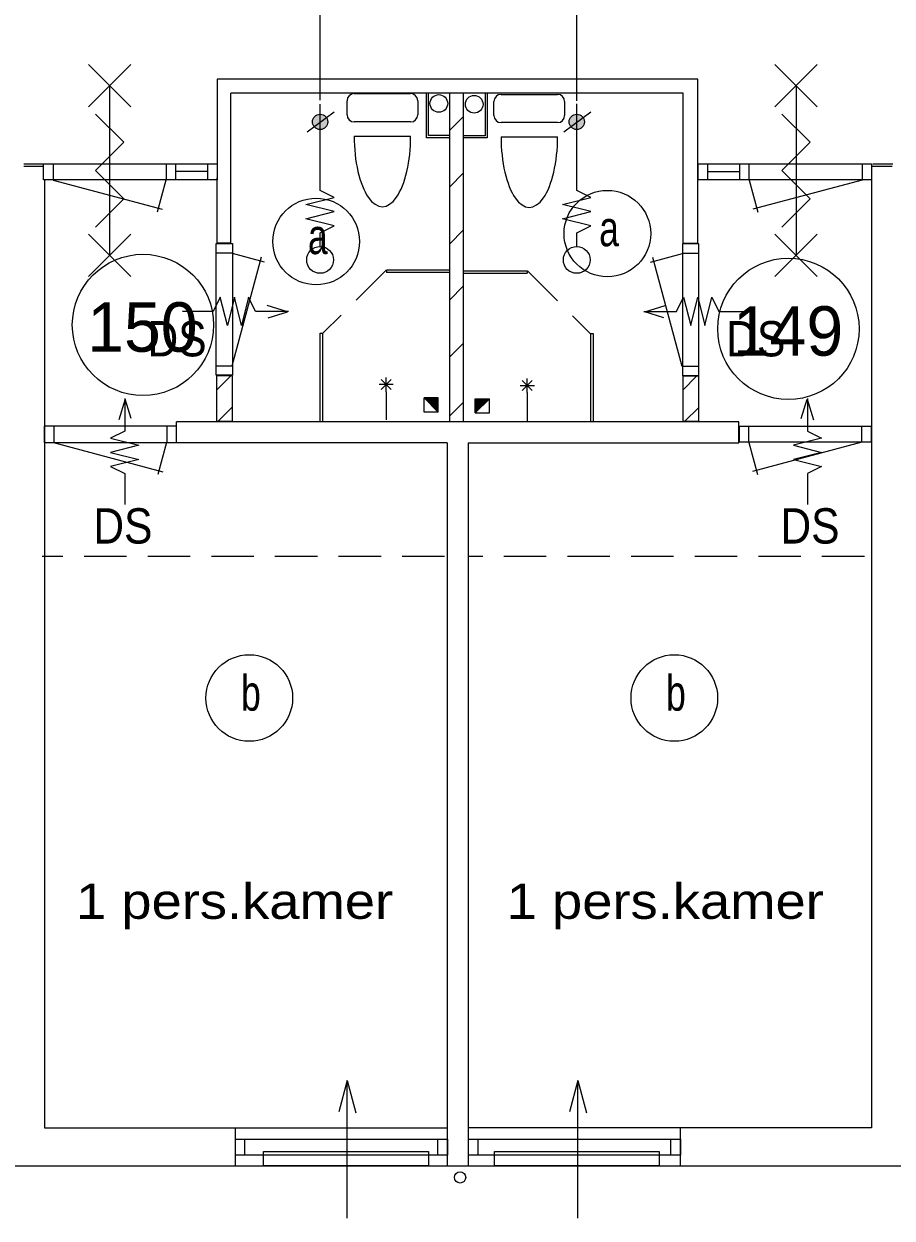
# Model space of a CAD drawing. Extents: x 295824 to 414724, y 24924 to 109024.
# Drawn here: x 313944 to 320086, y 61928 to 70382 of the extents above; entities that cross this region are included whole.
import ezdxf
from ezdxf.enums import TextEntityAlignment as Align

# ---------------------------------------------------------------- set-up
doc = ezdxf.new("R2010")
doc.units = 0
doc.header["$LTSCALE"] = 100
doc.linetypes.add('MEDIUM_DASHED', pattern=[4.5, 3, -1.5])
for name, color, linetype, lineweight in [('1', 7, 'Continuous', 13), ('16', 7, 'Continuous', 13), ('24', 7, 'Continuous', 13), ('61', 7, 'Continuous', 13)]:
    doc.layers.add(name, color=color, linetype=linetype, lineweight=lineweight)

msp = doc.modelspace()

# ---------------------------------------------------------------- hatches: boundary and pattern name
at = {"layer": '24'}
for points in [[(316094.1, 69688.9, 1), (315985.5, 69688.9, 1)], [(317909.6, 69688.9, 1), (317801, 69688.9, 1)]]:
    msp.add_hatch(color=256, dxfattribs=at).paths.add_polyline_path(points)
at = {"layer": '61'}
for points in [[(316775.3, 67734.4), (316875.3, 67634.4), (316875.3, 67734.4)], [(317237.7, 67729), (317137.7, 67629), (317137.7, 67729)]]:
    msp.add_hatch(color=256, dxfattribs=at).paths.add_polyline_path(points)

# ---------------------------------------------------------------- linework, layer by layer
at = {"layer": '1'}
for p, q in [((316039.8, 69843.4), (316039.8, 70726.3)), ((317855.3, 69838.4), (317855.3, 70726.3))]:
    msp.add_line(p, q, dxfattribs=at)
at = {"layer": '16'}
for p, q in [((315433.7, 68447.5), (315383.7, 68247.5)), ((318711.2, 68447.5), (318761.2, 68247.5)), ((314557.3, 67349.3), (314757.3, 67299.3)), ((319587.6, 67349.3), (319387.6, 67299.3))]:
    msp.add_line(p, q, dxfattribs=at)
at = {"layer": '24'}
for p, q in [((315948.2, 69618), (316139.7, 69759.7)), ((316039.8, 69253.4), (316039.8, 69814.2)), ((317763.7, 69618), (317955.2, 69759.7)), ((317855.3, 69253.4), (317855.3, 69815.7)), ((315809.1, 68344.1), (315665, 68389.2)), ((315673.3, 68301.7), (315809.1, 68344.1)), ((318335.8, 68344.1), (318480, 68389.2)), ((318471.6, 68301.7), (318335.8, 68344.1)), ((314660.7, 67724.8), (314615.7, 67580.6)), ((314703.1, 67588.9), (314660.7, 67724.8)), ((319441.8, 67588.9), (319484.2, 67724.8)), ((319484.2, 67724.8), (319529.2, 67580.6)), ((316231.3, 62903.3), (316171.7, 62680.9)), ((317863.6, 62903.3), (317804, 62680.9))]:
    msp.add_line(p, q, dxfattribs=at)
for points in [[(316039.8, 68803.4), (316039.8, 68903.4), (316139.8, 68953.4), (315939.8, 69003.4), (316139.8, 69053.4), (315939.8, 69103.4), (316139.8, 69153.4), (316039.8, 69203.4), (316039.8, 69253.4)], [(317855.3, 68803.4), (317855.3, 68903.4), (317955.3, 68953.4), (317755.3, 69003.4), (317955.3, 69053.4), (317755.3, 69103.4), (317955.3, 69153.4), (317855.3, 69203.4), (317855.3, 69253.4)], [(315383.7, 68247.5), (315333.7, 68447.5), (315283.7, 68347.5), (315065, 68347.5)], [(315815, 68347.5), (315583.7, 68347.5), (315533.7, 68447.5), (315483.7, 68247.5), (315433.7, 68447.5)], [(318330, 68347.5), (318561.2, 68347.5), (318611.2, 68447.5), (318661.2, 68247.5), (318711.2, 68447.5)], [(318761.2, 68247.5), (318811.2, 68447.5), (318861.2, 68347.5), (319079.9, 68347.5)], [(314657.3, 67730.6), (314657.3, 67499.3), (314557.3, 67449.3), (314757.3, 67399.3), (314557.3, 67349.3)], [(319487.6, 67730.6), (319487.6, 67499.3), (319587.6, 67449.3), (319387.6, 67399.3), (319587.6, 67349.3)], [(314757.3, 67299.3), (314557.3, 67249.3), (314657.3, 67199.3), (314657.3, 66980.6)], [(319387.6, 67299.3), (319587.6, 67249.3), (319487.6, 67199.3), (319487.6, 66980.6)], [(316231.3, 61928.3), (316231.3, 62903.3), (316293, 62673.1)], [(317863.6, 61928.3), (317863.6, 62903.3), (317925.3, 62673.1)]]:
    msp.add_lwpolyline(points, dxfattribs=at)
for points in [[(315640, 62399.1), (316805.9, 62399.1), (316805.9, 62299.1), (315640, 62299.1)], [(317272.3, 62399.1), (318438.2, 62399.1), (318438.2, 62299.1), (317272.3, 62299.1)]]:
    msp.add_lwpolyline(points, close=True, dxfattribs=at)
for centre, radius in [((316039.8, 69688.9), 54.3), ((317855.3, 69688.9), 54.3), ((316039.8, 68711.8), 95), ((317855.3, 68711.8), 95)]:
    msp.add_circle(centre, radius, dxfattribs=at)
at = {"layer": '61'}
for p, q in [((314400.3, 69794.2), (314700.3, 70094.2)), ((314700.3, 69794.2), (314400.3, 70094.2)), ((319256.2, 69794.2), (319556.2, 70094.2)), ((319556.2, 69794.2), (319256.2, 70094.2)), ((314550.3, 69944.2), (314550.3, 68744.2)), ((319406.2, 69944.2), (319406.2, 68744.2)), ((315407, 68829.5), (315407, 69891.5)), ((316230.2, 69738.5), (316230.2, 69838.5)), ((316280.2, 69888.5), (316680.2, 69888.5)), ((316730.2, 69838.5), (316730.2, 69738.5)), ((316807, 69591.5), (316807, 69891.5)), ((316957, 67566.5), (316957, 69891.5)), ((317053.3, 67566.5), (317053.3, 69891.5)), ((317207.1, 69891), (317207.1, 69591)), ((317269.6, 69733.6), (317269.6, 69833.6)), ((317319.6, 69883.6), (317719.6, 69883.6)), ((317769.6, 69833.6), (317769.6, 69733.6)), ((316680.2, 69688.5), (316280.2, 69688.5)), ((317052.8, 69725.6), (316957, 69629.8)), ((317719.6, 69683.6), (317319.6, 69683.6)), ((316280.2, 69588.5), (316680.2, 69588.5)), ((316957, 69591.5), (316807, 69591.5)), ((317207.1, 69591), (317057.1, 69591)), ((317319.6, 69583.6), (317719.6, 69583.6)), ((313944.8, 69391.4), (314086, 69391.4)), ((313944.8, 69376.4), (314086, 69376.4)), ((314150.8, 69391.4), (314150.8, 69277.4)), ((314950.8, 69391.4), (314950.8, 69277.4)), ((315017.8, 69391.4), (315017.8, 69277.4)), ((315243.8, 69337.3), (315017.8, 69337.3)), ((315243.8, 69391.4), (315243.8, 69277.4)), ((317052.8, 69324.7), (316957, 69228.9)), ((318712.3, 68828), (318712.3, 69393.9)), ((318780.5, 69391.4), (318780.5, 69277.4)), ((318780.5, 69337.4), (319006.5, 69337.4)), ((319006.5, 69391.4), (319006.5, 69277.4)), ((319073.5, 69391.4), (319073.5, 69277.4)), ((319873.5, 69391.4), (319873.5, 69277.4)), ((319944.4, 69376.4), (320085.5, 69376.4)), ((319949.3, 69391.4), (320090.5, 69391.4)), ((314090.1, 69276.6), (314090.1, 62566.5)), ((314150.1, 69276.8), (314922.8, 69069.7)), ((314948.5, 69276.2), (314887.7, 69049.3)), ((315312.3, 68829.5), (315312.3, 69291.5)), ((319075.8, 69276.2), (319136.6, 69049.3)), ((319874.2, 69276.8), (319101.5, 69069.8)), ((319940.1, 69291.5), (319940.1, 62566.5)), ((317052.8, 68921.3), (316957, 68825.5)), ((314400.3, 68594.2), (314700.3, 68894.2)), ((314700.3, 68594.2), (314400.3, 68894.2)), ((315304.8, 67894.7), (315304.8, 68828.7)), ((315407, 68829.5), (315312.3, 68829.5)), ((318712.3, 68828), (318607, 68828)), ((318718.2, 67892), (318718.2, 68824.4)), ((319256.2, 68594.2), (319556.2, 68894.2)), ((319556.2, 68594.2), (319256.2, 68894.2)), ((315304.8, 68761.7), (315418.8, 68761.7)), ((315416.8, 67960.9), (315623.9, 68733.6)), ((315417.5, 68759.3), (315644.3, 68698.5)), ((318600.4, 68755.1), (318373.6, 68694.3)), ((318718.2, 68757.4), (318604.2, 68757.4)), ((318601, 67956.6), (318394, 68729.4)), ((316958.1, 68640.1), (316508.7, 68640.1)), ((316508.7, 68640.1), (316508.7, 68622.1)), ((316957.8, 68622.1), (316508.7, 68622.1)), ((317054.8, 68634.8), (317504.3, 68634.8)), ((317055.2, 68616.8), (317504.3, 68616.8)), ((317504.3, 68634.8), (317504.3, 68616.8)), ((317052.8, 68525.3), (316957, 68429.5)), ((316057.8, 67572.1), (316057.8, 68192.6)), ((317955.2, 67566.7), (317955.2, 68187.2)), ((317052.8, 68120.7), (316957, 68024.9)), ((315418.2, 67894.7), (315304.2, 67894.7)), ((315304.8, 67961.7), (315418.8, 67961.7)), ((315417.5, 67891.1), (315307.5, 67891.1)), ((315307.5, 67891.1), (315307.5, 67567.1)), ((315407.2, 67889.9), (315307.5, 67790.2)), ((315417.5, 67891.1), (315417.5, 67567.1)), ((318718.2, 67957.4), (318604.2, 67957.4)), ((318705.6, 67889.9), (318605.9, 67790.2)), ((318716.4, 67891.1), (318606.5, 67891.1)), ((318606.5, 67891.1), (318606.5, 67567.1)), ((318716.4, 67891.1), (318716.4, 67567.1)), ((316557.6, 67828.6), (316457.6, 67828.6)), ((316543, 67793.2), (316472.3, 67863.9)), ((316543, 67863.9), (316472.3, 67793.2)), ((316507.6, 67778.6), (316507.6, 67878.6)), ((317455.3, 67823.2), (317555.3, 67823.2)), ((317470, 67787.9), (317540.7, 67858.6)), ((317470, 67858.6), (317540.7, 67787.9)), ((317505.3, 67773.2), (317505.3, 67873.2)), ((316507.6, 67778.6), (316507.6, 67578.6)), ((317505.3, 67773.2), (317505.3, 67573.2)), ((315415.8, 67667.3), (315316.1, 67567.6)), ((317052.8, 67702.6), (316957, 67606.8)), ((318717.9, 67667.3), (318618.2, 67567.6)), ((315417.5, 67567.1), (315307.5, 67567.1)), ((318716.4, 67567.1), (318606.5, 67567.1)), ((314155.4, 67534), (314155.4, 67420)), ((314955.4, 67534), (314955.4, 67420)), ((315022.4, 67534), (315022.4, 67420)), ((319003.1, 67535.1), (319003.1, 67421.1)), ((319070.1, 67535.1), (319070.1, 67421.1)), ((319870.1, 67535.1), (319870.1, 67421.1)), ((314154.6, 67419.4), (314927.4, 67212.3)), ((314953.1, 67418.7), (314892.3, 67191.9)), ((316940.1, 62296.5), (316940.1, 67416.5)), ((317090.1, 62296.5), (317090.1, 67416.5)), ((319072.4, 67419.8), (319133.2, 67193)), ((319870.8, 67420.4), (319098.1, 67213.4)), ((314090.1, 62566.5), (316940.1, 62566.5)), ((315441, 62295.2), (315441, 62565.2)), ((319940.1, 62566.5), (317090.1, 62566.5)), ((318589.5, 62295.3), (318589.5, 62565.3)), ((315508, 62373.6), (315508, 62487.5)), ((316873.1, 62373), (316873.1, 62487)), ((317156.6, 62373.9), (317156.6, 62487.9)), ((318520.9, 62373.6), (318520.9, 62487.3)), ((326233, 62296.5), (307806, 62296.5))]:
    msp.add_line(p, q, dxfattribs=at)
at = {"layer": '61', "linetype": 'MEDIUM_DASHED'}
for p, q in [((316506.6, 68639.6), (316059.7, 68192.8)), ((317506.4, 68634.3), (317953.2, 68187.4)), ((316920.4, 66613.1), (314073.3, 66613.1)), ((319889.8, 66613.1), (317090.1, 66613.1))]:
    msp.add_line(p, q, dxfattribs=at)
at = {"layer": '61'}
for points in [[(318712.3, 69391.5), (318712.3, 69991.5), (315312.3, 69991.5), (315312.3, 69391.5)], [(318607, 68828), (318607, 69891.5), (315407, 69891.5)], [(316957, 69576.5), (316792, 69576.5), (316792, 69891.5)], [(317222.1, 69891), (317222.1, 69576), (317057.1, 69576)], [(314450.3, 69744.2), (314650.3, 69544.2), (314450.3, 69344.2), (314650.3, 69144.2), (314450.3, 68944.2)], [(319306.2, 69744.2), (319506.2, 69544.2), (319306.2, 69344.2), (319506.2, 69144.2), (319306.2, 68944.2)], [(316039.8, 67572.1), (316039.8, 68192.6), (316057.8, 68192.6)], [(317973.2, 67566.7), (317973.2, 68187.2), (317955.2, 68187.2)], [(316875.3, 67634.4), (316875.3, 67734.4), (316775.3, 67734.4)], [(317137.7, 67629), (317137.7, 67729), (317237.7, 67729)], [(317087.3, 67416.5), (319002.3, 67416.5), (319002.3, 67566.5), (315022.9, 67566.5)], [(316937.3, 67416.5), (315022.9, 67416.5), (315022.9, 67566.5)], [(314088.4, 67534), (314088.4, 67420), (315022.4, 67420)], [(315022.4, 67534), (314088.4, 67534), (314088.4, 67420)], [(319937.1, 67535.1), (319937.1, 67421.1), (319003.1, 67421.1)], [(319003.1, 67535.1), (319937.1, 67535.1), (319937.1, 67421.1)]]:
    msp.add_lwpolyline(points, dxfattribs=at)
for points in [[(315310.8, 69391.4), (315310.8, 69277.4), (314083.8, 69277.4), (314083.8, 69391.4)], [(315310.9, 69391.4), (315310.9, 69277.4), (314083.9, 69277.4), (314083.9, 69391.4)], [(319940.5, 69391.4), (319940.5, 69277.4), (318714.1, 69277.4), (318714.1, 69391.4)], [(319940.5, 69391.4), (319940.5, 69277.4), (318714.1, 69277.4), (318714.1, 69391.4)], [(315304.8, 67894.7), (315304.8, 68828.7), (315418.8, 68828.7), (315418.8, 67894.7)], [(318718.2, 68825.4), (318604.2, 68825.4), (318604.2, 67891.4), (318718.2, 67891.4)], [(316875.3, 67634.4), (316775.3, 67634.4), (316775.3, 67734.4)], [(316775.3, 67734.4), (316875.3, 67634.4), (316875.3, 67734.4)], [(317137.7, 67629), (317237.7, 67629), (317237.7, 67729)], [(317237.7, 67729), (317137.7, 67629), (317137.7, 67729)], [(315441.2, 62373.5), (315441.2, 62487.5), (316939.9, 62487.5), (316939.9, 62373.5)], [(317090.2, 62373.6), (317090.2, 62487.6), (318589.6, 62487.6), (318589.6, 62373.6)]]:
    msp.add_lwpolyline(points, close=True, dxfattribs=at)
for centre, radius in [((316879.5, 69819.1), 62.5), ((317129.5, 69813.5), 62.5), ((318072, 68897.8), 306.3), ((316011.8, 68842), 306.3), ((314786.6, 68251.4), 500), ((319352.5, 68223.6), 500), ((315538.5, 65610.1), 306.3), ((318545.3, 65610.1), 306.3), ((317029.6, 62216.3), 40)]:
    msp.add_circle(centre, radius, dxfattribs=at)
for centre, start, end in [((316280.2, 69838.5), 90, 180), ((316680.2, 69838.5), 0, 90), ((317319.6, 69833.6), 90, 180), ((317719.6, 69833.6), 0, 90), ((316280.2, 69738.5), 180, 270), ((316680.2, 69738.5), 270, 0), ((317319.6, 69733.6), 180, 270), ((317719.6, 69733.6), 270, 0)]:
    msp.add_arc(centre, 50, start, end, dxfattribs=at)
for centre in [(316480.2, 69588.5), (317519.6, 69583.6)]:
    msp.add_ellipse(centre, major_axis=(0, -500), ratio=0.4, start_param=4.712389, end_param=7.853982, dxfattribs=at)

# ---------------------------------------------------------------- texts
at = {"layer": '24', "width": 0.9}
for p in [(314818.6, 68028.5), (318913, 68028.5), (314435.5, 66703.6), (319296.1, 66703.6)]:
    msp.add_text('DS', height=250, dxfattribs=at).set_placement(p)
at = {"layer": '61'}
for s, width, p in [('a', 0.75, (318014, 68808.6)), ('a', 0.75, (315953.8, 68752.8)), ('b', 0.75, (315480.5, 65520.9)), ('b', 0.75, (318487.3, 65520.9)), ('1 pers.kamer', 1.15, (314312.6, 64046.9)), ('1 pers.kamer', 1.15, (317359.4, 64046.9))]:
    msp.add_text(s, height=250, dxfattribs=dict(at, width=width)).set_placement(p)
for s, p in [('150', (314782.3, 68061.6)), ('149', (319349.6, 68033.7))]:
    msp.add_text(s, height=350, dxfattribs=at).set_placement(p, align=Align.CENTER)

doc.saveas('drawing.dxf')
